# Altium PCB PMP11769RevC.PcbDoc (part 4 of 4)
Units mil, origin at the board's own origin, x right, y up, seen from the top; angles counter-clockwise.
Board outline 7800 x 8510 mil, 4 copper layers (Top, Inner Top, Inner Bottom, Bottom), stack 33.235 mil thick; 451 components, 226 nets, 1199 pads, 1742 vias.
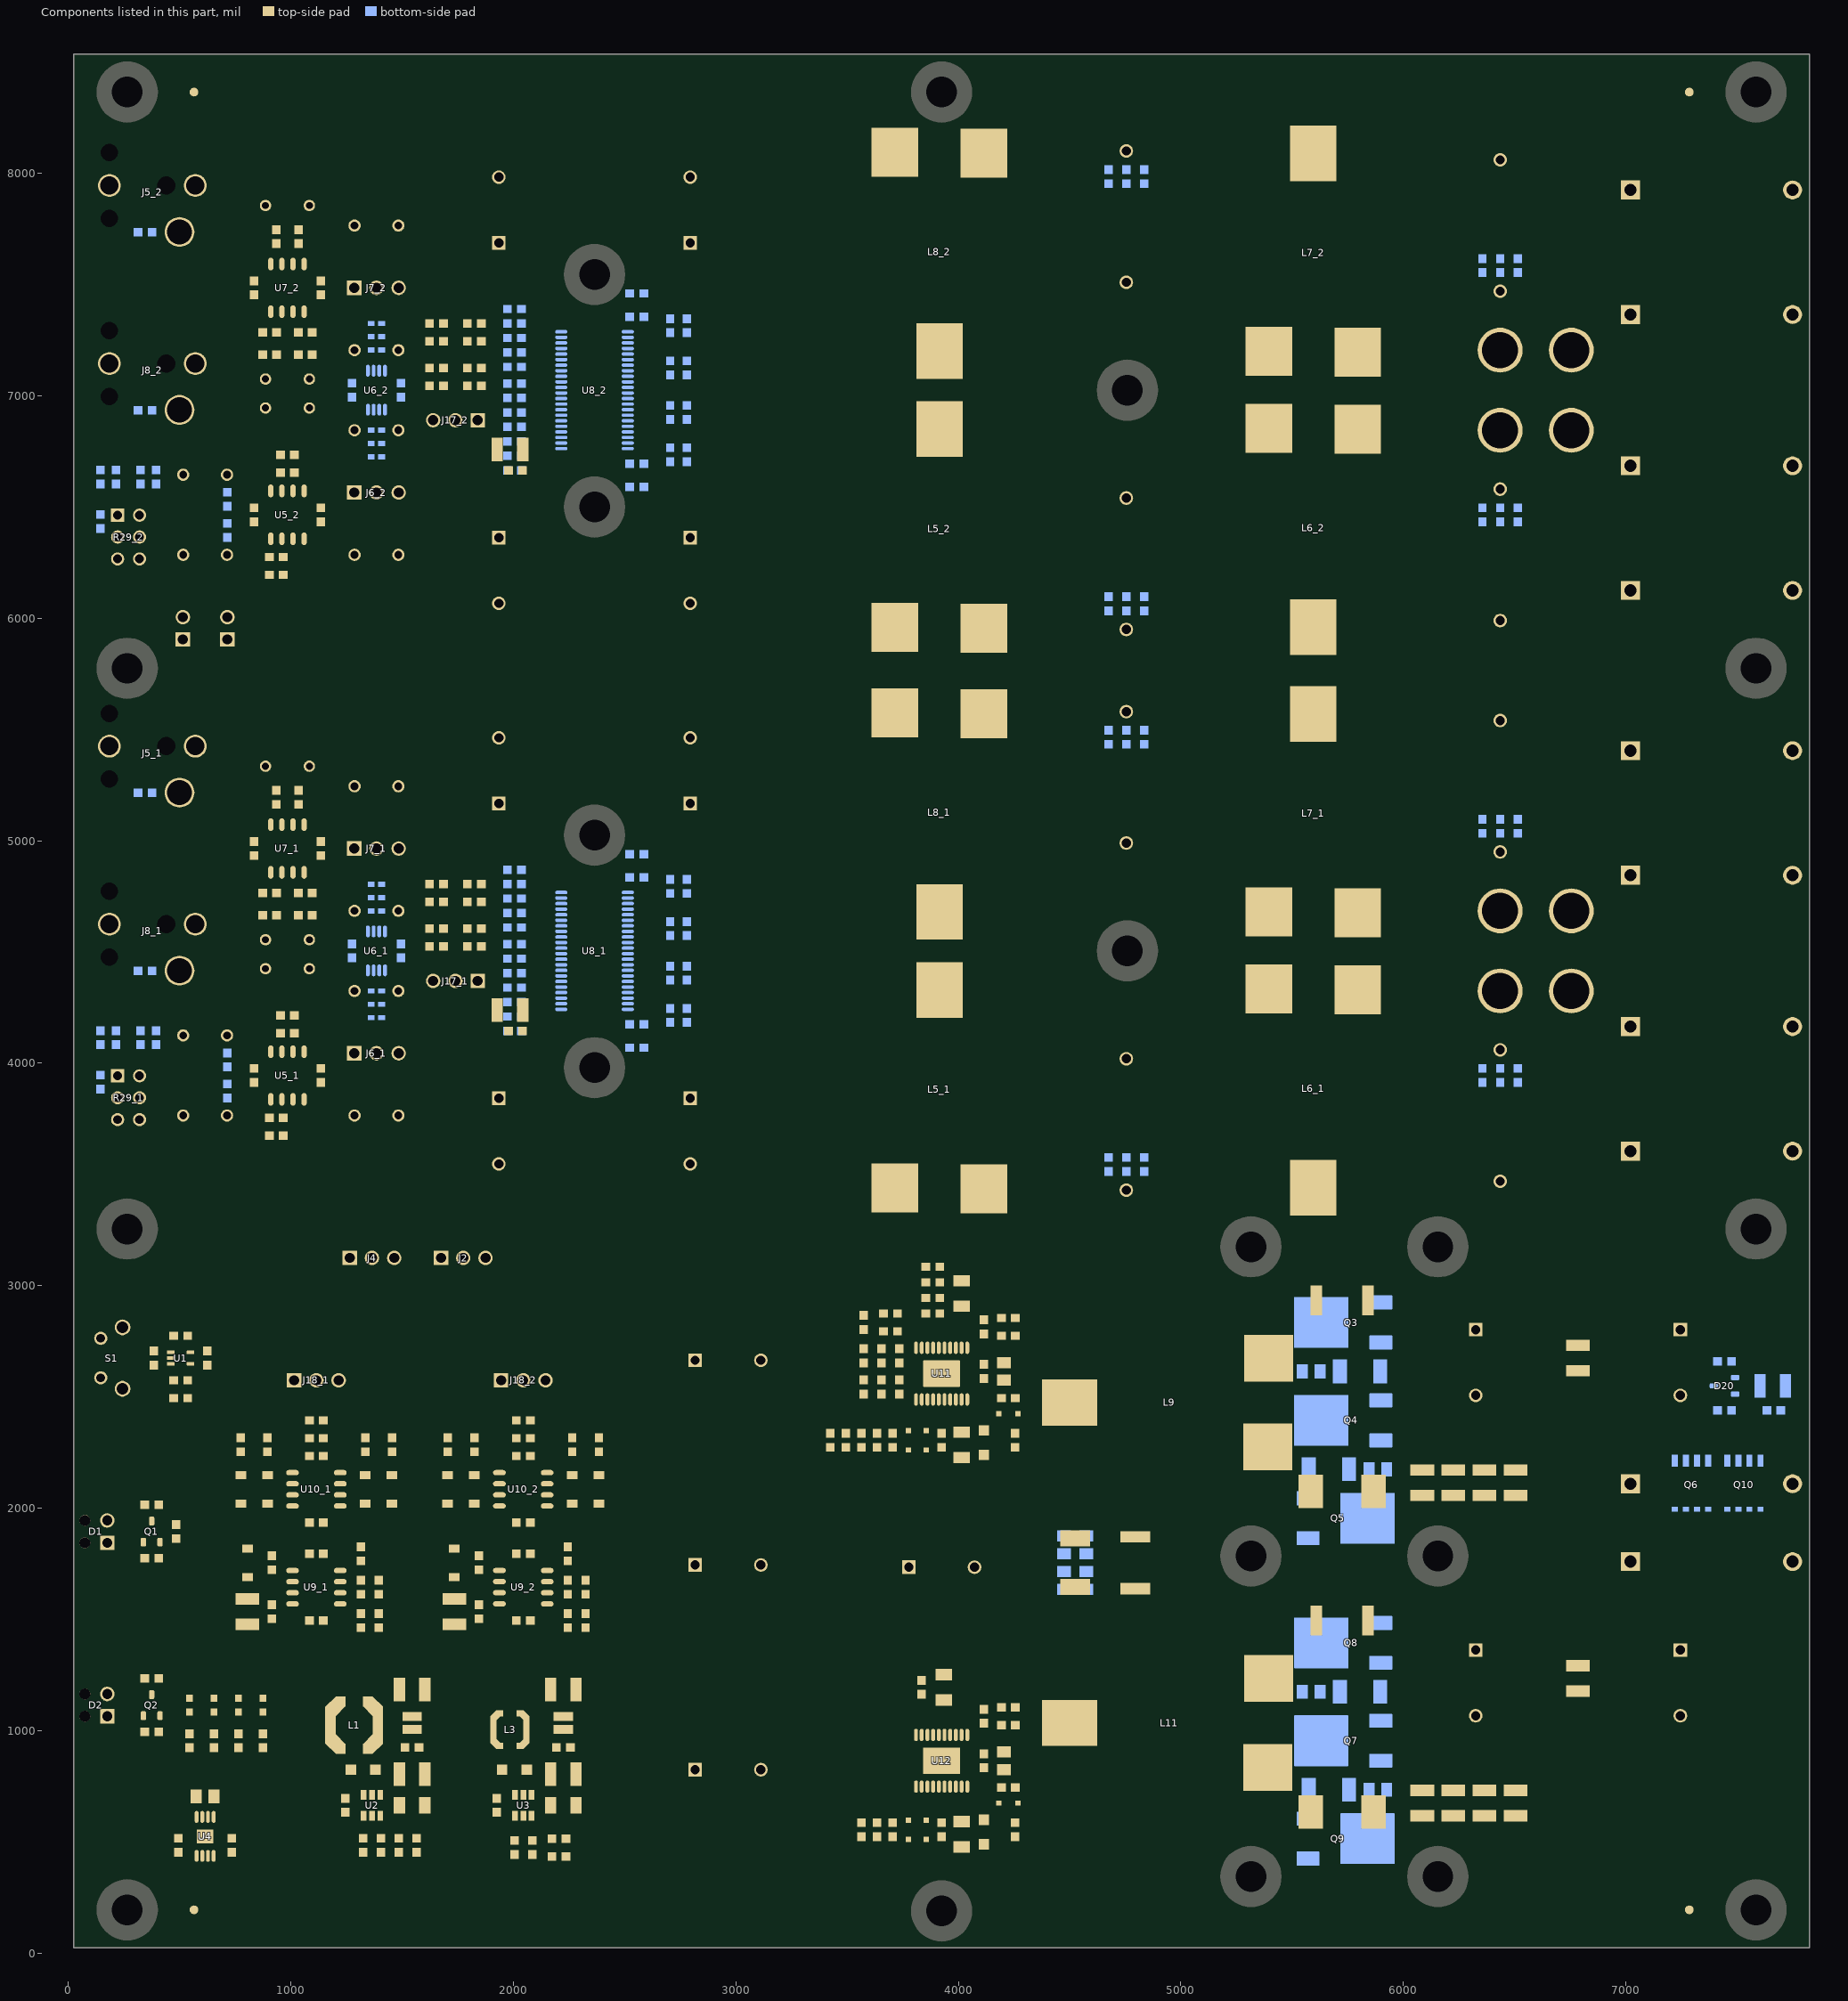
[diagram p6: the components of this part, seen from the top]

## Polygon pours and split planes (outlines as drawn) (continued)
GND on Top "Top-No Net 19" (solid, pour order 468): 6635,1775 6635,1645 5235,1645 5235,1775
GND on Top "Bottom-No Net 24" (solid, pour order 508): 3385,2135 3385,3175 5125,3175 5125,2135
VIN on Top "Top-No Net 14" (solid, pour order 493): 7425,3045 7825,3045 7825,1255 7425,1255
NetL11_2 on Top "Top-No Net 9" (solid, pour order 474): 5705,1605 5235,1605 5235,1095 5705,1095
SW-2 on Top "Top-No Net 10" (solid, pour order 484): 5705,1055 5235,1055 5235,345 5705,345
SW-1 on Top "Top-No Net 10" (solid, pour order 483): 5705,2495 5235,2495 5235,1815 5705,1815
NetL9_2 on Top "Top-No Net 9" (solid, pour order 473): 5705,3005 5235,3005 5235,2535 5705,2535
VIN on Top "Top-No Net 8" (solid, pour order 496): 7825,3175 7825,2695 5755,2695 5755,3175
NetC68_1_1 on Top "Bottom-No Net" (solid, remove dead copper, pour order 499): 7825,4525 7825,5105 5615,5105 5615,4525
NetC74_1_1 on Top "Bottom-No Net 1" (solid, remove dead copper, pour order 511): 7825,5695 3935,5695 3935,5145 7825,5145
NetC61_1_1 on Top "Bottom-No Net" (solid, remove dead copper, pour order 500): 7825,3905 7825,4485 5615,4485 5615,3905
NetC41_1_1 on Top "Bottom-No Net 1" (solid, remove dead copper, pour order 509): 7825,3325 3935,3325 3935,3865 7825,3865
NetC55_1_2 on Top "Top-No Net 2" (solid, remove dead copper, pour order 486): 3895,3325 3175,3325 3175,3865 3895,3865
NetC65_1_1 on Top "Top-No Net 2" (solid, remove dead copper, pour order 488): 3895,5145 3175,5145 3175,5695 3895,5695
NetC64_1_1 on Top "Top-No Net 3" (solid, remove dead copper, pour order 503): 3225,4525 5575,4525 5575,5105 3225,5105
NetC54_1_2 on Top "Top-No Net 3" (solid, remove dead copper, pour order 504): 3225,3905 5575,3905 5575,4485 3225,4485
NetC64_1_1 on Top "Top-No Net" (solid, remove dead copper, pour order 437): 2565,4575 2555,4565 2555,4525 2565,4515 2635,4515 2635,4575
NetC54_1_2 on Top "Top-No Net" (solid, remove dead copper, pour order 439): 2565,4495 2555,4485 2555,4445 2565,4435 2635,4435 2635,4495
NetC64_1_1 on Top "Top-No Net 4" (solid, pour order 469): 2630,4575 2640,4575 2660,4575 3190,5105 3230,5105 3230,4525 2660,4525 2650,4515 2630,4515
NetC54_1_2 on Top "Top-No Net 4" (solid, pour order 471): 2630,4435 2640,4435 2660,4435 3190,3905 3230,3905 3230,4485 2660,4485 2650,4495 2630,4495
NetC65_1_1 on Top "Top-No Net 6" (solid, pour order 480): 2625,4625 2660,4625 3180,5145 3180,5695 2855,5695 2855,5125 2625,4895
NetC55_1_2 on Top "Top-No Net 6" (solid, pour order 479): 2625,4385 2660,4385 3180,3865 3180,3325 2855,3325 2855,3885 2625,4115
NetC55_1_2 on Top "Top-No Net 1" (solid, pour order 451): 2555,4385 2555,4105 2635,4105 2635,4385
NetC65_1_1 on Top "Top-No Net 1" (solid, pour order 450): 2555,4905 2555,4625 2635,4625 2635,4905
GND on Top "Top-No Net 5" (solid, pour order 492): 1580,5325 1580,5695 2830,5695 2830,5325
GND on Top "Top-No Net 5" (solid, pour order 490): 1580,3325 1580,3685 2830,3685 2830,3325
GND on Top "Top-No Net 7" (solid, remove dead copper, pour order 515): 25,5695 25,3325 1860,3325 1860,3915 2477.5,3915 2477.5,5090 1860,5090 1860,5695
NetC95_2 on Top "Top-No Net 11" (solid, pour order 475): 6575,1815 6575,2095 5985,2095 5985,2175 5755,2175 5755,1815
VIN on Top "Top-No Net 8" (solid, pour order 494): 7820,1605 7820,1255 5755,1255 5755,1605
GND on Top "Top-No Net 12" (solid, pour order 497): 5755,1215 5755,775 6005,775 6005,695 7825,695 7825,1215
NetC95_2 on Top "Top-No Net 11" (solid, pour order 476): 6575,345 6575,655 5985,655 5985,735 5755,735 5755,345
GND on Top "Top-No Net 15" (solid, pour order 495): 5755,2655 5755,2215 6005,2215 6005,2135 6865,2135 6865,2195 7405,2195 7405,2655
GND on Top "Bottom-No Net 24" (solid, pour order 507): 3385,345 3385,1335 5125,1335 5125,345
GND on Top "Top-No Net 16" (solid, pour order 477): 6615,345 6615,715 7825,715 7825,605 7245,605 7245,345
VIN on Top "Top-No Net 17" (solid, pour order 460): 5775,3175 5775,3015 5235,3015 5235,3175
GND on Top "Top-No Net 18" (solid, pour order 462): 6615,2195 6615,1645 6865,1645 6865,2195
VIN on Top "Top-No Net 13" (solid, pour order 482): 6895,2155 7445,2155 7445,1585 6895,1585
VIN on Bottom "Bottom-No Net 5" (solid, pour order 621): 7665,2405 7525,2405 7525,2625 7665,2625
PVDD on Bottom "Bottom-No Net 2" (solid, remove dead copper, pour order 625): 2485,7083.7 2555,7083.7 2566.3,7095 2650,7095 2685,7130 2855,7130 2855,7310 2660,7310 2660,7275 2660,7178.7 2626.3,7145 2485,7145
GND on Bottom "Bottom-No Net 11" (solid, remove dead copper, pour order 647): 1560,8215 2870,8213.89 2870,5845 25,5845 25,8215
GND on Bottom "Bottom-No Net 9" (solid, remove dead copper, pour order 651): 2850,8215 2850,5845 7825,5845 7825,8215
PVDD on Bottom "Bottom-No Net 2" (solid, remove dead copper, pour order 626): 2485,6970 2550,6970 2565,6955 2655,6955 2690,6920 2855,6920 2855,6740 2660,6740 2660,6775 2660,6870 2625,6905 2485,6905
NetC64_2_1 on Bottom "Bottom-No Net 3" (solid, remove dead copper, pour order 603): 2485,7070 2485,7055 2560,7055 2570,7045 2625,7045 2635,7055 2635,7075 2625,7085 2570,7085 2555,7070
NetC54_2_2 on Bottom "Bottom-No Net 3" (solid, remove dead copper, pour order 602): 2485,6980 2485,6995 2560,6995 2570,7005 2625,7005 2635,6995 2635,6975 2625,6965 2571.04,6965 2556.04,6980
NetC55_2_2 on Bottom "Bottom-No Net 4" (solid, remove dead copper, pour order 605): 2485,6895 2485,6855 2622.5,6855 2632.5,6865 2632.5,6885 2622.5,6895
NetC65_2_1 on Bottom "Bottom-No Net 4" (solid, remove dead copper, pour order 608): 2485,7195 2485,7155 2622.5,7155 2632.5,7165 2632.5,7185 2622.5,7195
PVDD on Bottom "Bottom-No Net 31" (solid, pour order 623): 4340,1600 4340,1735 4420,1735 4420,1680 4435,1665 4615,1665 4628.07,1676.58 4630,1680 4630,1675 4630,1735 4710,1735 4710,1600
NetC95_2 on Bottom "Bottom-No Net 30" (solid, pour order 622): 4620,1845 4425,1845 4425,2000 4625,2000 4625,1845
GND on Bottom "Bottom-No Net 29" (solid, pour order 628): 915,3155 915,3345 1190,3345 1195,3350 1195,3155
GND on Bottom "Top-No Net 34" (solid, pour order 649): 25,3175 2545,3175 2545,345 25,345
NetC10_2 on Bottom "Bottom-No Net 28" (solid, pour order 629): 1985,535 2135,535 2135,890 1985,890
GND on Bottom "Bottom-No Net 27" (solid, pour order 638): 3465,5885 1585,5885 1585,5655 3465,5655
GND on Bottom "Bottom-No Net 24" (solid, pour order 645): 3385,2075 3385,3175 5195,3175 5195,2075
GND on Bottom "Bottom-No Net 20" (solid, pour order 644): 7825,2175 6005,2175 6005,2265 5835,2265 5835,3175 7825,3175
NetJ20_1 on Bottom "Bottom-No Net 19" (solid, pour order 631): 7825,2155 7825,1925 6960,1925 6960,2155
NetD17_2 on Bottom "Bottom-No Net 18" (solid, pour order 613): 5995,2965 5995,2885 5835,2885 5835,2965
NetD18_2 on Bottom "Bottom-No Net 18" (solid, pour order 612): 5995,2525 5995,2445 5835,2445 5835,2525
NetD19_2 on Bottom "Bottom-No Net 18" (solid, pour order 611): 5635,1905 5635,1825 5475,1825 5475,1905
NetC111_1 on Bottom "Bottom-No Net 14" (solid, pour order 619): 5875,675 5715,675 5715,795 5875,795
NetC95_2 on Bottom "Bottom-No Net 17" (solid, pour order 615): 5895,795 5985,795 5985,635 5895,635
NetC116_2 on Bottom "Bottom-No Net 14" (solid, pour order 618): 5755,1125 5595,1125 5595,1245 5755,1245
NetC95_1 on Bottom "Bottom-No Net 14" (solid, pour order 620): 5875,2115 5695,2115 5695,2235 5875,2235
NetC96_2 on Bottom "Bottom-No Net 14" (solid, pour order 617): 5755,2555 5595,2555 5595,2675 5755,2675
NetC65_1_1 on Bottom "Bottom-No Net 4" (solid, remove dead copper, pour order 607): 2485,4675 2485,4635 2622.5,4635 2632.5,4645 2632.5,4665 2622.5,4675
NetC55_1_2 on Bottom "Bottom-No Net 4" (solid, remove dead copper, pour order 606): 2485,4375 2485,4335 2622.5,4335 2632.5,4345 2632.5,4365 2622.5,4375
NetC54_1_2 on Bottom "Bottom-No Net 3" (solid, remove dead copper, pour order 601): 2485,4460 2485,4475 2560,4475 2570,4485 2625,4485 2635,4475 2635,4455 2625,4445 2571.04,4445 2556.04,4460
NetC64_1_1 on Bottom "Bottom-No Net 3" (solid, remove dead copper, pour order 604): 2485,4550 2485,4535 2560,4535 2570,4525 2625,4525 2635,4535 2635,4555 2625,4565 2570,4565 2555,4550
PVDD on Bottom "Bottom-No Net 2" (solid, remove dead copper, pour order 627): 2485,4450 2550,4450 2565,4435 2650,4435 2685,4400 2855,4400 2855,4220 2660,4220 2660,4255 2660,4350 2625,4385 2485,4385
GND on Bottom "Bottom-No Net 9" (solid, remove dead copper, pour order 650): 2850,5695 2850,3325 7825,3325 7825,5695
GND on Bottom "Bottom-No Net 11" (solid, remove dead copper, pour order 648): 1560,5695 2870,5693.89 2870,3325 25,3325 25,5695
SW-1 on Bottom "Bottom-No Net 15" (solid, pour order 640): 5805,3045 5805,2265 5655,2265 5655,1815 5235,1815 5235,3045
NetC95_2 on Bottom "Bottom-No Net 16" (solid, pour order 633): 5695,1815 6575,1815 6575,2095 5695,2095
NetC95_2 on Bottom "Bottom-No Net 17" (solid, pour order 616): 5895,2235 5985,2235 5985,2075 5895,2075
NetC95_2 on Bottom "Bottom-No Net 16" (solid, pour order 635): 5695,345 6575,345 6575,655 5695,655
NetD24_2 on Bottom "Bottom-No Net 18" (solid, pour order 614): 5635,465 5635,385 5475,385 5475,465
SW-2 on Bottom "Bottom-No Net 15" (solid, pour order 639): 5805,1515 5805,825 5655,825 5655,345 5235,345 5235,1515
NetD23_2 on Bottom "Bottom-No Net 18" (solid, pour order 610): 5995,1525 5995,1445 5835,1445 5835,1525
NetD22_2 on Bottom "Bottom-No Net 18" (solid, pour order 609): 5995,1085 5995,1005 5835,1005 5835,1085
GND on Bottom "Bottom-No Net 20" (solid, pour order 641): 7825,695 6005,695 6005,825 5835,825 5835,1585 7825,1585
GND on Bottom "Bottom-No Net 21" (solid, pour order 632): 6935,2195 6595,2195 6595,1565 6935,1565
GND on Bottom "Bottom-No Net 23" (solid, pour order 637): 6615,1795 6615,1555 5155,1555 5155,1795
GND on Bottom "Bottom-No Net 24" (solid, pour order 643): 3385,345 3385,1395 5195,1395 5195,345
GND on Bottom "Bottom-No Net 25" (solid, pour order 630): 5865,3075 5235,3075 5235,3175 5865,3175
GND on Bottom "Bottom-No Net 25" (solid, pour order 636): 7245,345 6615,345 6615,715 7825,715 7825,605 7245,605
GND on Bottom "Bottom-No Net 26" (solid, pour order 642): 5195,2095 5195,1375 2735,1375 2735,2095
GND on Bottom "Bottom-No Net 27" (solid, pour order 646): 3345,3365 2585,3365 2585,345 3345,345
PVDD on Bottom "Bottom-No Net 2" (solid, remove dead copper, pour order 624): 2485,4563.7 2555,4563.7 2566.3,4575 2650,4575 2685,4610 2855,4610 2855,4790 2660,4790 2660,4755 2660,4658.7 2626.3,4625 2485,4625
VIN on Bottom "Bottom-No Net 22" (solid, pour order 634): 6960,1905 6960,1610 7825,1610 7825,1905
NetC55_2_2 on Inner Top "Top-No Net 2" (solid, remove dead copper, pour order 544): 3895,5845 3175,5845 3175,6385 3895,6385
NetC55_2_2 on Inner Top "Top-No Net 1" (solid, pour order 520): 2552.01,6905 2552.01,6625 2632.01,6625 2632.01,6905
NetC55_2_2 on Inner Top "Top-No Net 6" (solid, pour order 539): 2625,6905 2660,6905 3180,6385 3180,5845 2855,5845 2855,6405 2625,6635
NetC65_2_1 on Inner Top "Top-No Net 2" (solid, remove dead copper, pour order 545): 3895,7665 3175,7665 3175,8215 3895,8215
NetC65_2_1 on Inner Top "Top-No Net 6" (solid, pour order 541): 2625,7145 2660,7145 3180,7665 3180,8215 2855,8215 2855,7645 2625,7415
NetC54_2_2 on Inner Top "Inner Top-No Net 9" (solid, pour order 547): 3635,6435 3195,6435 2675,6955 2555,6955 2555,7005 3635,7005
NetC64_2_1 on Inner Top "Inner Top-No Net 9" (solid, pour order 550): 3635,7615 3195,7615 2675,7095 2555,7095 2555,7045 3635,7045
NetC64_2_1 on Inner Top "Top-No Net 3" (solid, pour order 560): 3615,7055 5565,7055 5565,7615 3615,7615
NetC54_2_2 on Inner Top "Top-No Net 3" (solid, pour order 559): 3615,6435 5565,6435 5565,6995 3615,6995
NetC74_2_1 on Inner Top "Bottom-No Net 1" (solid, remove dead copper, pour order 569): 7825,7675 3945,7675 3945,8215 7825,8215
NetC41_2_1 on Inner Top "Bottom-No Net 1" (solid, remove dead copper, pour order 566): 7825,5845 3945,5845 3945,6375 7825,6375
NetC68_2_1 on Inner Top "Bottom-No Net" (solid, remove dead copper, pour order 563): 7825,7055 7825,7615 5615,7615 5615,7055
NetC61_2_1 on Inner Top "Bottom-No Net" (solid, remove dead copper, pour order 562): 7825,6435 7825,6995 5625,6995 5625,6435
NetC65_2_1 on Inner Top "Top-No Net 1" (solid, pour order 519): 2555.54,7424.4 2555.54,7144.4 2635.54,7144.4 2635.54,7424.4
PVDD on Inner Top "Inner Top-No Net 16" (solid, remove dead copper, pour order 525): 2830,6245 2830,6395 1900,6395 1900,6245
PVDD on Inner Top "Inner Top-No Net 16" (solid, remove dead copper, pour order 527): 2830,7650 2830,7800 1900,7800 1900,7650
PVDD on Inner Top "Inner Top-No Net 16" (solid, remove dead copper, pour order 524): 2830,5130 2830,5280 1900,5280 1900,5130
PVDD on Inner Top "Inner Top-No Net 16" (solid, remove dead copper, pour order 526): 2830,3725 2830,3875 1900,3875 1900,3725
NetC65_1_1 on Inner Top "Top-No Net 1" (solid, pour order 518): 2555.54,4904.4 2555.54,4624.4 2635.54,4624.4 2635.54,4904.4
PVDD on Inner Top "Inner Top-No Net 14" (solid, pour order 570): 2585,3175 3345,3175 3345,345 2585,345
PVDD on Inner Top "Inner Top-No Net 13" (solid, pour order 565): 4685,1375 2635,1375 2635,2095 4345,2095 4345,1735 4685,1735
NetC95_2 on Inner Top "Inner Top-No Net 12" (solid, pour order 528): 4385,2055 4385,1775 4925,1775 4925,2055
VIN on Inner Top "Inner Top-No Net 8" (solid, pour order 551): 7425,1255 7825,1255 7825,3045 7425,3045
SW-1 on Inner Top "Inner Top-No Net 7" (solid, pour order 530): 5235,2075 5705,2075 5705,2495 5235,2495
GND on Inner Top "Inner Top-No Net 6" (solid, pour order 521): 6105,2885 6105,2625 5755,2625 5755,2885
VIN on Inner Top "Inner Top-No Net" (solid, pour order 555): 5755,3175 5755,2965 6135,2965 6135,2695 7825,2695 7825,3175
VIN on Inner Top "Inner Top-No Net 3" (solid, pour order 534): 6895,2155 7445,2155 7445,1685 6895,1685
NetC95_2 on Inner Top "Inner Top-No Net 2" (solid, pour order 533): 5755,2175 5985,2175 5985,2095 6575,2095 6575,1815 5758.54,1815 5755,1818.54
NetL9_2 on Inner Top "Inner Top-No Net 1" (solid, pour order 540): 5705,3175 5705,2535 5235,2535 5235,3175
NetC61_1_1 on Inner Top "Bottom-No Net" (solid, remove dead copper, pour order 561): 7825,3915 7825,4475 5625,4475 5625,3915
NetC68_1_1 on Inner Top "Bottom-No Net" (solid, remove dead copper, pour order 564): 7825,4535 7825,5095 5615,5095 5615,4535
NetC41_1_1 on Inner Top "Bottom-No Net 1" (solid, remove dead copper, pour order 567): 7825,3325 3945,3325 3945,3855 7825,3855
NetC74_1_1 on Inner Top "Bottom-No Net 1" (solid, remove dead copper, pour order 568): 7825,5155 3945,5155 3945,5695 7825,5695
NetC54_1_2 on Inner Top "Top-No Net 3" (solid, pour order 558): 3615,3915 5565,3915 5565,4475 3615,4475
NetC64_1_1 on Inner Top "Top-No Net 3" (solid, pour order 557): 3615,4535 5565,4535 5565,5095 3615,5095
NetL11_2 on Inner Top "Inner Top-No Net 1" (solid, pour order 536): 5705,1705 5705,1095 5235,1095 5235,1705
SW-2 on Inner Top "Inner Top-No Net 7" (solid, pour order 529): 5235,635 5705,635 5705,1055 5235,1055
VIN on Inner Top "Inner Top-No Net" (solid, pour order 553): 5755,1705 5755,1525 6135,1525 6135,1255 7825,1255 7825,1705
NetC95_2 on Inner Top "Inner Top-No Net 2" (solid, pour order 535): 5755,735 5985,735 5985,655 6575,655 6575,345 5755,345
GND on Inner Top "Inner Top-No Net 5" (solid, pour order 556): 5755,1215 5755,775 6005,775 6005,695 7825,695 7825,1215
GND on Inner Top "Inner Top-No Net 6" (solid, pour order 522): 6105,1445 6105,1185 5755,1185 5755,1445
NetC64_1_1 on Inner Top "Inner Top-No Net 9" (solid, pour order 549): 3635,5095 3195,5095 2675,4575 2555,4575 2555,4525 3635,4525
NetC54_1_2 on Inner Top "Inner Top-No Net 9" (solid, pour order 548): 3635,3915 3195,3915 2675,4435 2555,4435 2555,4485 3635,4485
NetC65_1_1 on Inner Top "Top-No Net 6" (solid, pour order 542): 2625,4625 2660,4625 3180,5145 3180,5695 2855,5695 2855,5125 2625,4895
NetC65_1_1 on Inner Top "Top-No Net 2" (solid, remove dead copper, pour order 546): 3895,5145 3175,5145 3175,5695 3895,5695
NetC55_1_2 on Inner Top "Top-No Net 6" (solid, pour order 538): 2625,4385 2660,4385 3180,3865 3180,3325 2855,3325 2855,3885 2625,4115
NetC55_1_2 on Inner Top "Top-No Net 1" (solid, pour order 517): 2552.01,4385 2552.01,4105 2632.01,4105 2632.01,4385
NetC55_1_2 on Inner Top "Top-No Net 2" (solid, remove dead copper, pour order 543): 3895,3325 3175,3325 3175,3865 3895,3865
GND on Inner Top "Top-No Net 15" (solid, pour order 552): 5755,2655 5755,2215 6005,2215 6005,2135 6865,2135 6865,2195 7365,2195 7365,2655
NetC95_2 on Inner Top "Inner Top-No Net 10" (solid, pour order 531): 5775,2055 4885,2055 4885,1815 5775,1815
NetC95_2 on Inner Top "Inner Top-No Net 10" (solid, pour order 532): 5775,615 4885,615 4885,345 5775,345
GND on Inner Top "Bottom-No Net 25" (solid, pour order 537): 7244.6,345 6615,345 6615,715 7825,715 7825,605 7245,605
GND on Inner Top "Top-No Net 18" (solid, pour order 523): 6615,2195 6615,1815 6865,1815 6865,2195
NetC95_2 on Inner Top "Inner Top-No Net 11" (solid, pour order 554): 5195,2055 5195,345 4710,345 4710,2055
GND on Inner Bottom "Inner Bottom-No Net 11" (solid, pour order 571): 2865,4415 2865,4595 2540,4595 2540,4415
GND on Inner Bottom "Inner Bottom-No Net 11" (solid, pour order 572): 2865,6935 2865,7115 2540,7115 2540,6935
GND on Inner Bottom "Inner Bottom-No Net 10" (solid, pour order 596): 2560,5280 2560,3725 2075,3725 2075,5280
GND on Inner Bottom "Inner Bottom-No Net 10" (solid, pour order 595): 2560,7800 2560,6245 2075,6245 2075,7800
NetC41_2_1 on Inner Bottom "Inner Bottom-No Net" (solid, pour order 594): 6295,6985 6575,6985 6575,6365 7215,6365 7215,5845 6295,5845
NetC74_2_1 on Inner Bottom "Inner Bottom-No Net" (solid, pour order 589): 6615,7065 6895,7065 6895,7685 7215,7685 7215,8205 6615,8205
GND on Inner Bottom "Inner Bottom-No Net 9" (solid, pour order 579): 3345,2475 3025,2475 3025,3175 3345,3175
PVDD on Inner Bottom "Inner Top-No Net 15" (solid, remove dead copper, pour order 600): 2581.2,7800 2581.2,2556.42 2985,2556.42 2985,3215 3345,3215 3345,7800
GND on Inner Bottom "Inner Bottom-No Net 8" (solid, pour order 588): 3995,1375 3995,1795 4865,1795 4945,1795 4945,1375
GND on Inner Bottom "Inner Bottom-No Net 7" (solid, pour order 598): 2585,2515 3345,2515 3345,345 2585,345
GND on Inner Bottom "Inner Bottom-No Net 5" (solid, pour order 574): 5845,2785 4935,2785 4935,2985 5755,2985 5755,2885 5845,2885
VIN on Inner Bottom "Top-No Net 14" (solid, pour order 587): 7425,3045 7825,3045 7825,2195 7425,2195
GND on Inner Bottom "Inner Bottom-No Net 3" (solid, pour order 573): 5835,2885 6105,2885 6105,2625 5835,2625
VIN on Inner Bottom "Inner Bottom-No Net 1" (solid, pour order 592): 5865,3045 5865,2965 6135,2965 6135,2695 7825,2695 7825,3045
GND on Inner Bottom "Inner Top-No Net 4" (solid, pour order 591): 5835,2655 5835,2215 6005,2215 6005,2135 6935,2135 6935,2655
NetC95_2 on Inner Bottom "Top-No Net 11" (solid, pour order 582): 6575,1815 6575,2095 5985,2095 5985,2175 5755,2175 5755,1815
SW-1 on Inner Bottom "Bottom-No Net 15" (solid, pour order 586): 5755,2725 5755,2265 5705,2265 5705,2075 5235,2075 5235,2725
NetC74_1_1 on Inner Bottom "Inner Bottom-No Net" (solid, pour order 590): 6615,4545 6895,4545 6895,5165 7215,5165 7215,5685 6615,5685
NetC41_1_1 on Inner Bottom "Inner Bottom-No Net" (solid, pour order 593): 6295,4465 6575,4465 6575,3845 7215,3845 7215,3325 6295,3325
SW-2 on Inner Bottom "Bottom-No Net 15" (solid, pour order 585): 5755,1285 5755,825 5705,825 5705,635 5235,635 5235,1057.17 5462.83,1285
NetC95_2 on Inner Bottom "Top-No Net 11" (solid, pour order 584): 6575,345 6575,655 5985,655 5985,735 5755,735 5755,345
GND on Inner Bottom "Inner Top-No Net 4" (solid, pour order 599): 5835,1585 5835,775 6005,775 6005,695 7825,695 7825,1585
GND on Inner Bottom "Inner Bottom-No Net 4" (solid, pour order 576): 6595,2195 6935,2195 6935,1585 6595,1585
GND on Inner Bottom "Bottom-No Net 23" (solid, pour order 597): 6615,1795 6615,1335 4905,1335 4905,1795
NetC95_2 on Inner Bottom "Inner Top-No Net 10" (solid, pour order 581): 5775,615 4905,615 4905,345 5775,345
NetC95_2 on Inner Bottom "Inner Top-No Net 10" (solid, pour order 578): 5775,2055 4905,2055 4905,1815 5775,1815
GND on Inner Bottom "Inner Bottom-No Net 6" (solid, pour order 575): 4905,1355 4905,1035 5495,1035 5495,1355
GND on Inner Bottom "Inner Bottom-No Net 2" (solid, pour order 580): 7405,2655 7405,2195 6915,2195 6915,2655
NetJ20_1 on Inner Bottom "Bottom-No Net 19" (solid, pour order 577): 7825,2155.45 7825,1915 6960,1915 6960,2155.45
VIN on Inner Bottom "Bottom-No Net 22" (solid, pour order 583): 6960,1905 6960,1610 7825,1610 7825,1905

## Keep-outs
Keep-Out Layer:
  text ".Layer_Name" at -3888,-1283.49 h60

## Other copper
Top:
  text "1" at 7325,425 h100
  text ".Layer_Name" at -3888,-1283.49 h60
Inner Top:
  text "2" at 7425,425 h100
Inner Bottom:
  text "3" at 7555,425 h100
Bottom:
  text "4" at 7685,425 h100
  text ".Layer_Name" at -3888,-1283.49 h60

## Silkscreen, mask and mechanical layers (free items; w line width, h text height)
Top Overlay:
  circle w10: c995,8135 r5
  circle w10: c1110,8135 r5
  circle w10: c2068,2795 r3
  circle w10: c1984,2795 r3
  circle w10: c1158,2795 r3
  circle w10: c1075,2795 r3
  circle w10: c1370,2925 r5
  circle w10: c1175,2925 r5
  circle w10: c1110,5615 r5
  circle w10: c995,5615 r5
  circle w10: c1110,8135 r5
  circle w10: c995,8135 r5
  rectangle: 6955,365 7115,475
  lines w10: 6435,4450 6435,4560 ; 6755,6970 6755,7080 ; 6760,4450 6760,4560 ; 6760,6970 6760,7080 ; 6435,6970 6435,7080 6435,6970
  text "Amplifier 2" at 715,8065 h70
  text "S" at 1270,7375 h40
  text "M" at 1475,7375 h40
  text "OPEN:  Stereo" at 7010,7085 h50
  text "SHORT: Mono" at 7010,6915 h50
  text "S" at 1625,6775 h40
  text "M" at 1825,6775 h40
  text "S" at 1270,6455 h40
  text "M" at 1475,6455 h40
  text "OPEN:  4-Channel" at 795,5985 h50
  text "SHORT: 2-Channel" at 795,5875 h50
  text "Amplifier 1" at 715,5545 h70
  text "S" at 1270,4855 h40
  text "M" at 1475,4855 h40
  text "OPEN:  Stereo" at 7010,4565 h50
  text "SHORT: Mono" at 7010,4395 h50
  text "S" at 1625,4255 h40
  text "M" at 1825,4255 h40
  text "S" at 1270,3935 h40
  text "M" at 1475,3935 h40
  text "M" at 1250,3015 h40
  text "P" at 1350,3015 h40
  text "P" at 1450,3015 h40
  text "M" at 1660,3015 h40
  text "M" at 1760,3015 h40
  text "P" at 1860,3015 h40
  text "Clipping Detector" at 1035,2855 h70
  text "Amplifier 1" at 875,2745 h50
  text "Amplifier 2" at 1785,2745 h50
  text "RESET" at 90,2470 h50 r270
  text "L" at 1000,2465 h40
  text "R" at 1200,2465 h40
  text "L" at 1930,2465 h40
  text "R" at 2135,2465 h40
  text "-" at 7625,2315 h200
  text "FAULT" at 100,1735 h50 r270
  text "+" at 7625,1365 h200
  text "+3.3V" at 565,1215 h40 r90
  text "-12V" at 675,1215 h40 r90
  text "+12V" at 785,1215 h40 r90
  text "+36V" at 893.72,1215.48 h40 r90
  text "CLIP" at 100,955 h50 r270
  text "PMP11769" at 6675,515 h70
  text "Rev." at 6675,385 h70
  text ".Layer_Name" at -3888,-1283.49 h60
Bottom Overlay:
  drawing of 3645 lines, arcs and shapes, not listed
  text ".Layer_Name" at -3888,-1283.49 h60
Top Paste:
  text ".Layer_Name" at -3888,-1283.49 h60
Bottom Paste:
  text ".Layer_Name" at -3888,-1283.49 h60
Top Solder:
  text ".Layer_Name" at -3888,-1283.49 h60
  text ".Layer_Name" at -3888,-1283.49 h60
Bottom Solder:
  drawing of 628 lines, arcs and shapes, not listed
  text ".Layer_Name" at -3888,-1283.49 h60
Drill Guide:
  text ".Layer_Name" at -3888,-1283.49 h60
Mechanical 1:
  lines w10: 0,0 0,8560 7850,8560 7850,0 0,0
  text ".Layer_Name" at -3888,-1283.49 h60
Mechanical 2:
  text ".Layer_Name" at -3888,-1283.49 h60
Mechanical 3:
  text ".Layer_Name" at -3888,-1283.49 h60
Mechanical 4:
  text ".Layer_Name" at -3888,-1283.49 h60
Mechanical 5:
  lines w10: -4757,-1355.17 1843,-1355.17 ; -4757,-1151.83 1845,-1151.83 ; -4757,-948.5 -4757,-1558.5 -752,-1558.5 1845,-1558.5 1845,-948.5 -4756.5,-948.5 -4756.5,-1558.5 -3181,-1558.5 ; -2292,-1558.5 -2292,-948.5 ; -1025,-1151.83 -1025,-948.5 ; -185,-1151.83 -185,-948.5 ; 437,-1565 437,-1362.17
  text "PCB VIEWED FROM TOP SIDE" at -4693.5,-1080.67 h60
  text "BOARD #:" at -2217,-1080.67 h60
  text ".PRJ_Number" at -1671.5,-1080.67 h60
  text "REV:" at -827,-1080.67 h60
  text ".PCB_Rev" at -535.5,-1080.67 h60
  text "SVN REV:" at 11,-1080.67 h60
  text ".VersionControl_RevNumber" at 517,-1080.67 h60
  text "IGNORE ->" at -4693.5,-1283.49 h60
  text "PLOT NAME =" at -4693.5,-1489.34 h60
  text ".plot_File_Name" at -3888,-1489.34 h60
  text "GENERATED    :" at -2215,-1489.34 h60
  text ".Print_Date" at -1345.5,-1489.34 h60
  text ".Print_Time" at -616.5,-1489.34 h60
  text "TEXAS INSTRUMENTS" at 648,-1489.34 h60
Mechanical 6:
  lines w10: -4757.5,-1152.33 1844.5,-1152.33 ; -4755.5,-1355.67 1844.5,-1355.67 ; -3349.5,-1565.5 -3349.5,-1362.67 ; -2727.5,-1152.33 -2727.5,-949 ; -1887.5,-1152.33 -1887.5,-949 ; -620.5,-1559 -620.5,-949 ; 25,115 25,3515 ; 268.5,-1559 1844,-1559 1844,-949 -4757.5,-949 -4757.5,-1559 -2160.5,-1559 1844.5,-1559 1844.5,-949
  text ".VersionControl_RevNumber" at -3429.5,-1081.17 h60
  text "SVN REV:" at -2923.5,-1081.17 h60
  text ".PCB_Rev" at -2377,-1081.17 h60
  text "REV:" at -2085.5,-1081.17 h60
  text ".PRJ_Number" at -1241,-1081.17 h60
  text "BOARD #:" at -695.5,-1081.17 h60
  text "PCB VIEWED FROM BOTTOM SIDE" at 1781,-1081.17 h60
  text "IGNORE ->" at -1917.15,-1283.49 h60
  text "TEXAS INSTRUMENTS" at -3560.5,-1489.84 h60
  text ".Print_Time" at -2296,-1489.84 h60
  text ".Print_Date" at -1567,-1489.84 h60
  text "GENERATED    :" at -697.5,-1489.84 h60
  text ".plot_File_Name" at 975.5,-1489.84 h60
  text "PLOT NAME =" at 1781,-1489.84 h60
Mechanical 9:
  lines w10: -4956.5,616.5 -4756.5,616.5 ; -4956.5,5366.5 -4756.5,5366.5 ; -2456.5,-1758.5 -2456.5,-1558.5 ; -2456.5,10025 -2456.5,10225 ; 15,10025 15,10225 ; 43.5,-1758.5 43.5,-1558.5 ; 1856,-1558.5 1856,-948.5 6838.5,-948.5 ; 2533.5,-1758.5 2533.5,-1558.5 ; 2535,10011.5 2535,10211.5 ; 2535,10025 2535,10225 ; 2543.5,-1758.5 2543.5,-1558.5 ; 5033.5,-1758.5 5033.5,-1558.5 ; 5035,10011.5 5035,10211.5 ; 5043.5,-1758.5 5043.5,-1558.5 ; 6838.5,-1558.5 6838.5,-948.5 ; 6838.5,-1248.5 9838.5,-1248.5 ; 7533.5,-1758.5 7533.5,-1558.5 ; 7543.5,-1758.5 7543.5,-1558.5 ; 7545,10011.5 7545,10211.5 ; 8343.5,-1548.5 8343.5,-948.5 ; 9838.5,-948.5 6838.5,-948.5 ; 9843.5,-358.5 9843.5,-1558.5 -4756.5,-1558.5 -4756.5,10025 9843.5,10025 ; 9845,-1558.5 9845,10025 ; -4956.5,-1758.5 10043.5,-1758.5 10043.5,10225 -4956.5,10225 -4956.5,-1758.5
  text "1" at -3725.16,10095 h70
  text "2" at -1229.5,10095 h70
  text "3" at 1245,10095 h70
  text "4" at 3758.01,10081.5 h70
  text "5" at 6257,10081.5 h70
  text "6" at 8772,10081.5 h70
  text "A" at -4881.5,6468.5 h70
  text "D" at -4881.5,-656.5 h70
  text "Texas Instruments (TI) and/or its licensors do not warrant the accuracy or completeness of this specification" at 1909,-1030.34 h45
  text "ENGINEER:" at 6878.5,-1038.5 h45
  text "LAYOUT BY:" at 8383.5,-1038.5 h45
  text "or any information contained therein. TI and/or its licensors do not warrant that this design will meet" at 1864.01,-1143 h45
  text ".PRJ_Engineer" at 6928.5,-1193.49 h70
  text ".PCB_Layout" at 8434,-1193.49 h70
  text "the specifications, will be suitable for your application or fit for any particular purpose, or will operate in" at 1864.01,-1255.67 h45
  text ".Layer_Name" at -3888,-1283.49 h60
  text "ALTIUM DESIGNER VERSION:" at 8383.5,-1348.5 h45
  text "an implementation. TI and/or its licensors do not warrant that the design is production worthy. You should" at 1864.01,-1368.33 h45
  text "completely validate and test your design implementation to confirm the system functionality for your application." at 1909,-1481 h45
  text ".print_Scale" at 6928.5,-1481.83 h70
  text ".Application_BuildNumber" at 8434,-1481.83 h70
  text "1" at -3725.16,-1688.5 h70
  text "2" at -1229.5,-1688.5 h70
  text "3" at 1259.84,-1688.5 h70
  text "4" at 3756.51,-1688.5 h70
  text "4" at 3766.51,-1688.5 h70
  text "5" at 6255.5,-1688.5 h70
  text "5" at 6265.5,-1688.5 h70
  text "6" at 8760.5,-1688.5 h70
  text "6" at 8770.5,-1688.5 h70
  text "6" at 8320.5,-1708.5 h70
Mechanical 10:
  text ".Layer_Name" at -3888,-1283.49 h60
Mechanical 11:
  lines w10: -4757,-1355.17 1843,-1355.17 ; -4757,-1151.83 1845,-1151.83 ; -4757,-948.5 -4757,-1558.5 -752,-1558.5 1845,-1558.5 1845,-948.5 -4756.5,-948.5 -4756.5,-1558.5 -3181,-1558.5 ; -2292,-1558.5 -2292,-948.5 ; -1025,-1151.83 -1025,-948.5 ; -185,-1151.83 -185,-948.5 ; 437,-1565 437,-1362.17
  text "ALL ARTWORK VIEWED FROM TOP SIDE" at -4693.5,-1080.67 h60
  text "BOARD #:" at -2217,-1080.67 h60
  text ".PRJ_Number" at -1671.5,-1080.67 h60
  text "REV:" at -827,-1080.67 h60
  text ".PCB_Rev" at -535.5,-1080.67 h60
  text "SVN REV:" at 11,-1080.67 h60
  text ".VersionControl_RevNumber" at 517,-1080.67 h60
  text "LAYER NAME =" at -4693.5,-1283.49 h60
  text "PLOT NAME =" at -4693.5,-1489.34 h60
  text ".plot_File_Name" at -3888,-1489.34 h60
  text "GENERATED    :" at -2215,-1489.34 h60
  text ".Print_Date" at -1345.5,-1489.34 h60
  text ".Print_Time" at -616.5,-1489.34 h60
  text "TEXAS INSTRUMENTS" at 648,-1489.34 h60
Mechanical 12:
  text ".Layer_Name" at -3888,-1283.49 h60
Mechanical 13:
  text ".Layer_Name" at -3888,-1283.49 h60
Mechanical 14:
  text ".Layer_Name" at -3888,-1283.49 h60
Mechanical 15:
  text ".Layer_Name" at -3888,-1283.49 h60
Mechanical 16:
  text ".Layer_Name" at -3888,-1283.49 h60
Drill Drawing:
  text ".Layer_Name" at -3888,-1283.49 h60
